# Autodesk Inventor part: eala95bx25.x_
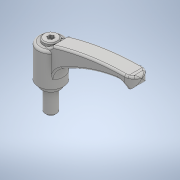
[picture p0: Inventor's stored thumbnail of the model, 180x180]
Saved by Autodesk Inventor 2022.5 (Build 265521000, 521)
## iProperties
Created: 2018-05
Part Number: eala95bx25.x_
Material: 一般
Document SubType Name: Modeling
Designer: imaocorp
Density: 1 g/cm^3
Appearance: 既定
Sending System: SOLIDWORKS 2016-2016286
MC: AMD64
MC_MODEL: AMD64 Family 21 Model 2 Stepping 0, AuthenticAMD
OS: Windows_NT
FRU: Parasolid Version 28.0, build 224,  7-29-2016
FORMAT: text
GUISE: transmit
KEY: eala95bx25
FILE: eala95bx25.x_t
DATE: Fri May 18 11:33:44 2018
Author: imaocorp
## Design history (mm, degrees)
feature "Base1"
node "ソリッド1"
